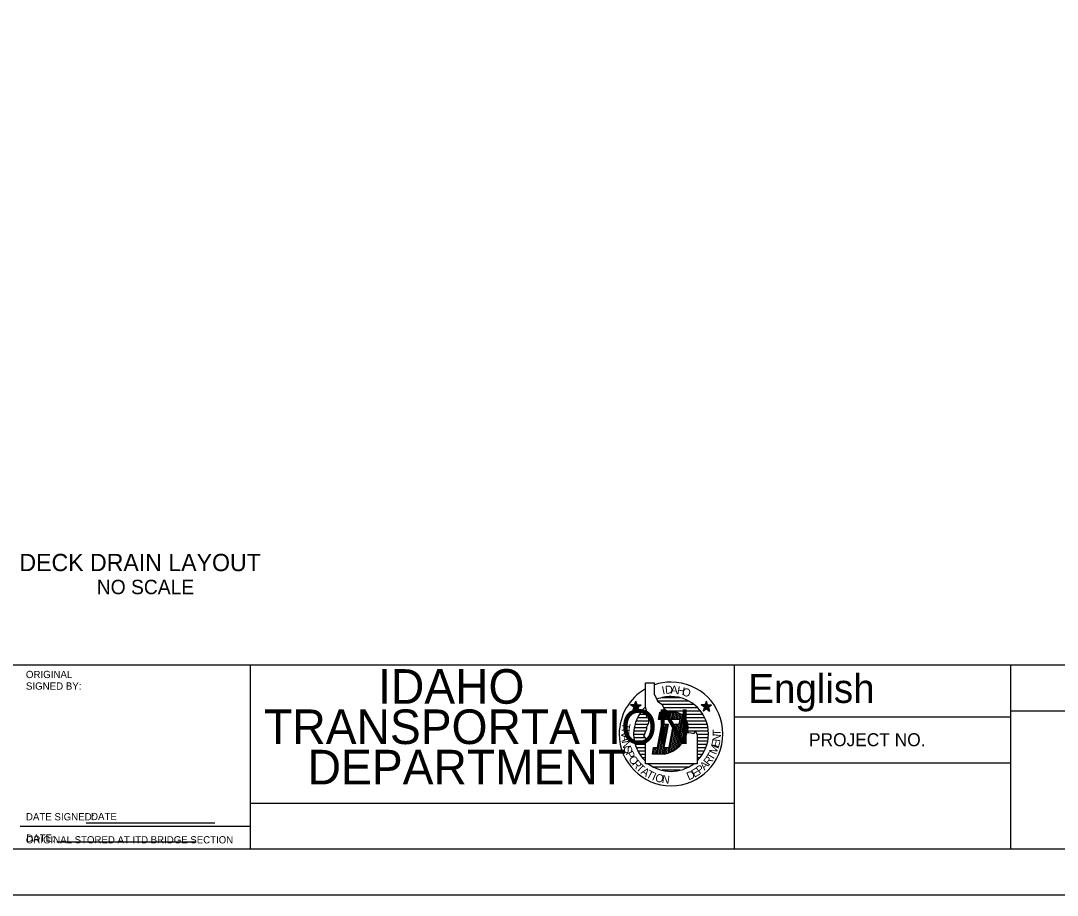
# Model space of a CAD drawing. Extents: x 0 to 22.7, y 0 to 15.7.
# Drawn here: x 7.67 to 15.17, y 0 to 6.33 of the extents above; entities that cross this region are included whole.
import ezdxf

# ---------------------------------------------------------------- set-up
doc = ezdxf.new("R2010")
doc.units = 0
for name, color, linetype in [('BORDER_ANNO_Cutsheet', 7, 'Continuous'), ('BRDG_ANNO_Anno-Large-Print', 7, 'Continuous'), ('BRDG_ANNO_Anno-Sheet', 7, 'Continuous'), ('BRDG_ANNO_Anno-Small-Print', 7, 'Continuous'), ('BRDG_ANNO_General-Notes', 7, 'Continuous')]:
    doc.layers.add(name, color=color, linetype=linetype)

msp = doc.modelspace()

# ---------------------------------------------------------------- linework, layer by layer
at = {"layer": 'BORDER_ANNO_Cutsheet'}
msp.add_lwpolyline([(0, 14.6667), (22.6667, 14.6667), (22.6667, 0), (0, 0)], close=True, dxfattribs=at)
at = {"layer": 'BRDG_ANNO_Anno-Large-Print'}
msp.add_line((7.9329, 0.3871), (8.9371, 0.3871), dxfattribs=at)
at = {"layer": 'BRDG_ANNO_Anno-Sheet'}
for p, q in [((1, 1.6667), (12.8333, 1.6667)), ((9.3333, 0.3333), (9.3333, 1.6667)), ((12.8333, 0.3333), (12.8333, 1.6667)), ((12.8333, 1.6667), (22.3333, 1.6667)), ((14.8333, 0.3333), (14.8333, 1.6667)), ((12.1896, 1.3617), (12.1896, 1.5354)), ((12.1896, 1.5354), (12.2554, 1.5354)), ((12.2554, 1.4487), (12.2554, 1.5354)), ((12.2554, 1.4487), (12.2729, 1.4175)), ((12.31, 1.4296), (12.4387, 1.4296)), ((12.1342, 1.36), (12.0817, 1.3771)), ((12.1104, 1.3771), (12.0817, 1.3771)), ((12.105, 1.36), (12.0817, 1.3771)), ((12.1288, 1.3771), (12.0958, 1.3321)), ((12.105, 1.36), (12.0958, 1.3321)), ((12.105, 1.36), (12.1579, 1.3771)), ((12.1104, 1.3771), (12.1196, 1.4046)), ((12.1104, 1.3771), (12.1433, 1.3321)), ((12.1196, 1.3492), (12.1196, 1.4046)), ((12.1288, 1.3771), (12.1196, 1.4046)), ((12.1288, 1.3771), (12.1579, 1.3771)), ((12.1342, 1.36), (12.1579, 1.3771)), ((12.1342, 1.36), (12.1433, 1.3321)), ((12.1829, 1.3575), (12.1908, 1.3575)), ((12.1962, 1.3375), (12.1896, 1.3617)), ((12.2729, 1.4175), (12.2762, 1.4033)), ((12.2762, 1.4033), (12.3108, 1.3792)), ((12.2779, 1.4054), (12.5004, 1.4054)), ((12.31, 1.3817), (12.5379, 1.3817)), ((12.3108, 1.3792), (12.3217, 1.3513)), ((12.3192, 1.3575), (12.5671, 1.3575)), ((12.3217, 1.3513), (12.3562, 1.3237)), ((12.645, 1.36), (12.5921, 1.3771)), ((12.6158, 1.36), (12.5921, 1.3771)), ((12.6212, 1.3771), (12.5921, 1.3771)), ((12.6396, 1.3771), (12.6067, 1.3321)), ((12.6158, 1.36), (12.6067, 1.3321)), ((12.6158, 1.36), (12.6683, 1.3771)), ((12.6212, 1.3771), (12.6304, 1.4046)), ((12.6212, 1.3771), (12.6542, 1.3321)), ((12.6304, 1.3492), (12.6304, 1.4046)), ((12.6396, 1.3771), (12.6304, 1.4046)), ((12.6396, 1.3771), (12.6683, 1.3771)), ((12.645, 1.36), (12.6683, 1.3771)), ((12.645, 1.36), (12.6542, 1.3321)), ((12.1196, 1.3492), (12.0958, 1.3321)), ((12.1196, 1.3492), (12.1433, 1.3321)), ((12.1312, 1.2854), (12.1988, 1.2854)), ((12.1446, 1.3096), (12.195, 1.3096)), ((12.1612, 1.3337), (12.1958, 1.3337)), ((12.1962, 1.3167), (12.1962, 1.3375)), ((12.1962, 1.2992), (12.1962, 1.3167)), ((12.2, 1.2854), (12.1962, 1.2992)), ((12.2137, 1.2783), (12.2, 1.2854)), ((12.2137, 1.2608), (12.2137, 1.2783)), ((12.2833, 1.2712), (12.2937, 1.3237)), ((12.2929, 1.2712), (12.3025, 1.3237)), ((12.2937, 1.3237), (12.4083, 1.3237)), ((12.3033, 1.2712), (12.3133, 1.3237)), ((12.3142, 1.2712), (12.3238, 1.3237)), ((12.3246, 1.2712), (12.3346, 1.3237)), ((12.335, 1.2712), (12.345, 1.3237)), ((12.3438, 1.3337), (12.5883, 1.3337)), ((12.3458, 1.2712), (12.3554, 1.3237)), ((12.3562, 1.2712), (12.3662, 1.3237)), ((12.3671, 1.2712), (12.3767, 1.3237)), ((12.3775, 1.2712), (12.3875, 1.3237)), ((12.3883, 1.2712), (12.3979, 1.3237)), ((12.3987, 1.2712), (12.4087, 1.3237)), ((12.3996, 1.0496), (12.4479, 1.3079)), ((12.4092, 1.2712), (12.4187, 1.3208)), ((12.4117, 1.0571), (12.4575, 1.3013)), ((12.42, 1.2712), (12.4287, 1.3179)), ((12.4242, 1.0671), (12.4662, 1.2925)), ((12.4304, 1.2712), (12.4383, 1.3133)), ((12.4371, 1.0792), (12.475, 1.2829)), ((12.4458, 1.3096), (12.605, 1.3096)), ((12.4733, 1.2854), (12.6183, 1.2854)), ((12.6304, 1.3492), (12.6067, 1.3321)), ((12.6304, 1.3492), (12.6542, 1.3321)), ((12.8333, 1.2917), (14.8333, 1.2917)), ((14.8333, 1.3333), (20.1667, 1.3333)), ((12.1083, 1.2137), (12.1988, 1.2137)), ((12.1137, 1.2375), (12.2075, 1.2375)), ((12.1208, 1.2617), (12.2125, 1.2617)), ((12.1896, 1.1812), (12.2, 1.2021)), ((12.2, 1.2192), (12.2067, 1.2333)), ((12.2, 1.2021), (12.2, 1.2192)), ((12.2067, 1.2333), (12.2137, 1.2504)), ((12.2137, 1.2504), (12.2137, 1.2608)), ((12.2762, 1.07), (12.3075, 1.2367)), ((12.2775, 1.0212), (12.3179, 1.2367)), ((12.4408, 1.2712), (12.2833, 1.2712)), ((12.2883, 1.0212), (12.3287, 1.2367)), ((12.2988, 1.0212), (12.3392, 1.2367)), ((12.3075, 1.2367), (12.3533, 1.2367)), ((12.3096, 1.0212), (12.35, 1.2367)), ((12.3533, 1.2367), (12.3221, 1.07)), ((12.3625, 1.07), (12.3937, 1.2367)), ((12.3646, 1.0317), (12.4029, 1.2367)), ((12.3758, 1.0367), (12.4133, 1.2367)), ((12.3875, 1.0421), (12.4242, 1.2367)), ((12.3937, 1.2367), (12.4346, 1.2367)), ((12.4346, 1.2367), (12.4408, 1.2712)), ((12.4504, 1.0933), (12.4833, 1.2708)), ((12.4646, 1.1125), (12.4912, 1.2546)), ((12.4812, 1.145), (12.4971, 1.23)), ((12.4883, 1.2617), (12.6288, 1.2617)), ((12.4962, 1.2375), (12.6363, 1.2375)), ((12.4983, 1.2137), (12.6417, 1.2137)), ((12.1042, 1.1654), (12.185, 1.1654)), ((12.105, 1.1896), (12.1937, 1.1896)), ((12.1054, 1.1417), (12.1875, 1.1417)), ((12.1792, 1.15), (12.1858, 1.1671)), ((12.1896, 1.1396), (12.1792, 1.15)), ((12.1858, 1.1671), (12.1896, 1.1812)), ((12.1962, 1.1292), (12.1896, 1.1396)), ((12.2, 1.1221), (12.1962, 1.1292)), ((12.4938, 1.185), (12.4987, 1.1775)), ((12.495, 1.1896), (12.645, 1.1896)), ((12.4987, 1.1775), (12.5196, 1.1742)), ((12.5196, 1.1742), (12.5404, 1.1708)), ((12.5404, 1.1708), (12.5508, 1.1846)), ((12.5508, 1.1846), (12.5646, 1.1638)), ((12.5633, 1.1654), (12.6458, 1.1654)), ((12.5646, 1.1638), (12.5646, 0.9517)), ((12.565, 1.1417), (12.6446, 1.1417)), ((12.1087, 1.1175), (12.1988, 1.1175)), ((12.1142, 1.0938), (12.1892, 1.0938)), ((12.1225, 1.0696), (12.1883, 1.0696)), ((12.1896, 1.1013), (12.2, 1.1117)), ((12.1896, 0.9517), (12.1896, 1.1013)), ((12.2, 1.1117), (12.2, 1.1221)), ((12.2396, 1.0212), (12.2487, 1.07)), ((12.2458, 1.0212), (12.255, 1.07)), ((12.2487, 1.07), (12.2762, 1.07)), ((12.2567, 1.0212), (12.2658, 1.07)), ((12.2671, 1.0212), (12.2762, 1.07)), ((12.32, 1.0212), (12.3292, 1.07)), ((12.3221, 1.07), (12.3625, 1.07)), ((12.3308, 1.0217), (12.34, 1.07)), ((12.3421, 1.0246), (12.3504, 1.07)), ((12.3533, 1.0279), (12.3608, 1.07)), ((12.5646, 1.1175), (12.6412, 1.1175)), ((12.5646, 1.0938), (12.6358, 1.0938)), ((12.5646, 1.0696), (12.6275, 1.0696)), ((12.1329, 1.0454), (12.1883, 1.0454)), ((12.1467, 1.0217), (12.1887, 1.0217)), ((12.1638, 0.9975), (12.1883, 0.9975)), ((12.3283, 1.0212), (12.2396, 1.0212)), ((12.5646, 1.0454), (12.6167, 1.0454)), ((12.5646, 1.0217), (12.6033, 1.0217)), ((12.5646, 0.9975), (12.5867, 0.9975)), ((12.185, 0.9738), (12.1892, 0.9738)), ((12.5646, 0.9517), (12.1896, 0.9517)), ((12.5004, 0.9275), (12.2479, 0.9275)), ((12.4392, 0.9037), (12.3117, 0.9037)), ((12.8333, 0.9583), (14.8333, 0.9583)), ((9.3333, 0.6667), (12.8333, 0.6667))]:
    msp.add_line(p, q, dxfattribs=at)
msp.add_lwpolyline([(1, 14.3333), (22.3333, 14.3333), (22.3333, 0.3333), (1, 0.3333)], close=True, dxfattribs=at)
for centre, radius, start, end in [((12.375, 1.1667), 0.375, 90, 108.596), ((12.375, 1.1667), 0.375, 0, 90), ((12.375, 1.1667), 0.375, 119.63312, 180), ((12.375, 1.1667), 0.2708, 90, 112.14518), ((12.375, 1.1667), 0.2708, 0, 90), ((12.375, 1.1667), 0.2708, 133.19257, 180), ((12.3888, 1.2161), 0.1094, 343.49805, 79.73615), ((12.375, 1.1667), 0.375, 180, 270), ((12.375, 1.1667), 0.2708, 180.26444, 226.79463), ((12.2899, 1.2255), 0.2078, 280.64795, 348.77185), ((12.375, 1.1667), 0.375, 270, 0), ((12.375, 1.1667), 0.2708, 314.427, 0), ((12.375, 1.1667), 0.2708, 232.5658, 270), ((12.375, 1.1667), 0.2708, 270, 307.45359)]:
    msp.add_arc(centre, radius, start, end, dxfattribs=at)
at = {"layer": 'BRDG_ANNO_Anno-Small-Print'}
for p, q in [((7.6667, 0.5), (9.3333, 0.5)), ((8.1442, 0.5242), (9.0758, 0.5242))]:
    msp.add_line(p, q, dxfattribs=at)

# ---------------------------------------------------------------- texts
at = {"layer": 'BRDG_ANNO_Anno-Large-Print'}
msp.add_text('DATE:', height=0.05248, dxfattribs=at).set_placement((7.71, 0.3871))
at = {"layer": 'BRDG_ANNO_Anno-Sheet'}
for s, height, p in [('IDAHO', 0.25, (10.2558, 1.3854)), ('English', 0.20833, (12.9337, 1.3912)), ('TRANSPORTATION', 0.25, (9.4313, 1.0938)), ('PROJECT NO.', 0.09375, (13.3728, 1.0783)), ('DEPARTMENT', 0.25, (9.7462, 0.8021))]:
    msp.add_text(s, height=height, dxfattribs=at).set_placement(p)
for s, rotation, p in [('I', 11.95188, (12.3146, 1.4521)), ('D', 5.21184, (12.3342, 1.4563)), ('A', 357.8718, (12.3712, 1.4587)), ('H', 349.63177, (12.4146, 1.4558)), ('O', 342.19173, (12.4496, 1.4487)), ('T', 259.42648, (12.0254, 1.2504)), ('R', 266.0275, (12.0175, 1.205)), ('A', 273.76404, (12.0154, 1.1604)), ('N', 83.19321, (12.73, 1.1087)), ('T', 90.49256, (12.7346, 1.1529)), ('N', 280.37584, (12.0192, 1.1142)), ('S', 287.92792, (12.0287, 1.0692)), ('M', 67.71394, (12.7004, 1.0137)), ('E', 75.61046, (12.7196, 1.0646)), ('P', 295.49755, (12.0437, 1.0271)), ('O', 302.64464, (12.0637, 0.9867)), ('R', 309.90789, (12.0892, 0.9483)), ('R', 52.33438, (12.6492, 0.9342)), ('T', 59.03624, (12.6758, 0.97)), ('T', 317.1211, (12.1183, 0.9142)), ('A', 324.63754, (12.1521, 0.8837)), ('T', 331.75026, (12.1896, 0.8579)), ('E', 30.54757, (12.5437, 0.8492)), ('P', 37.66562, (12.5821, 0.8729)), ('A', 45, (12.6171, 0.9004)), ('I', 337.0213, (12.2329, 0.8358)), ('O', 343.32869, (12.255, 0.8271)), ('N', 351.65981, (12.3058, 0.8133)), ('D', 22.98872, (12.5021, 0.8304))]:
    msp.add_text(s, height=0.0579, rotation=rotation, dxfattribs=at).set_placement(p)
at = {"layer": 'BRDG_ANNO_Anno-Small-Print'}
for s, height, p in [('ORIGINAL', 0.0525, (7.7083, 1.5708)), ('SIGNED BY:', 0.0525, (7.7083, 1.4871)), ('DATE SIGNED:', 0.0525, (7.7083, 0.5417)), ('DATE', 0.05248, (8.1792, 0.5437)), ('ORIGINAL STORED AT ITD BRIDGE SECTION', 0.052144, (7.7083, 0.3752))]:
    msp.add_text(s, height=height, dxfattribs=at).set_placement(p)
at = {"layer": 'BRDG_ANNO_General-Notes'}
for s, height, p in [('DECK DRAIN LAYOUT', 0.125, (7.6612, 2.3444)), ('NO SCALE', 0.10417, (8.2209, 2.1778))]:
    msp.add_text(s, height=height, dxfattribs=at).set_placement(p)

doc.saveas('drawing.dxf')
